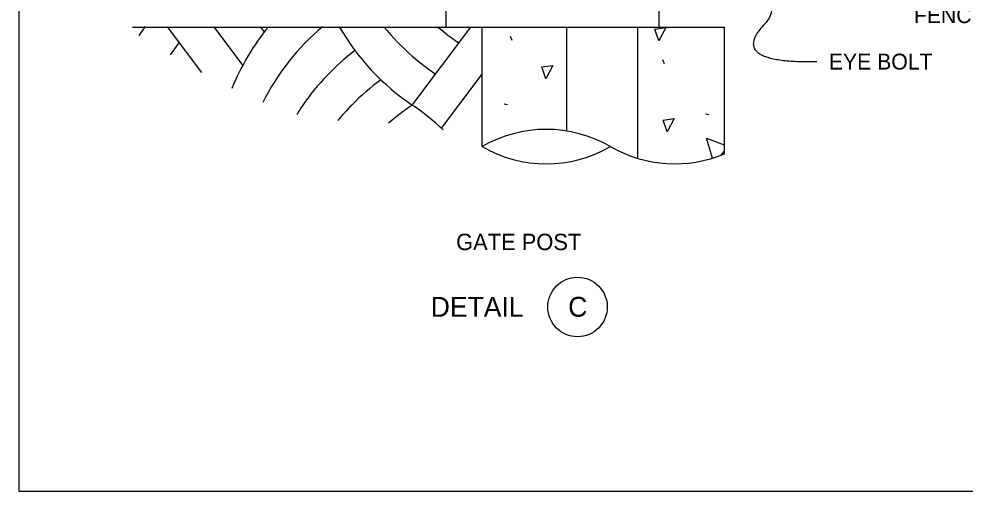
# Model space of a CAD drawing. Extents: x 99862 to 104211, y 98939 to 105076.
# Drawn here: x 99862 to 100816, y 103000 to 103475 of the extents above; entities that cross this region are included whole.
import ezdxf

# ---------------------------------------------------------------- set-up
doc = ezdxf.new("R2010")
doc.units = 0
for name, color, linetype in [('Level 1', 7, 'Continuous'), ('Level 10', 7, 'Continuous'), ('Level 15', 7, 'Continuous'), ('Level 20', 7, 'Continuous'), ('Level 6', 7, 'Continuous'), ('Level 60', 7, 'Continuous'), ('Level 7', 7, 'Continuous'), ('Level 9', 7, 'Continuous')]:
    doc.layers.add(name, color=color, linetype=linetype)

msp = doc.modelspace()

# ---------------------------------------------------------------- linework, layer by layer
at = {"layer": 'Level 1'}
msp.add_lwpolyline([(99862, 102999.5), (103151, 102999.5), (103151, 105075.5), (99862, 105075.5)], close=True, dxfattribs=at)
at = {"layer": 'Level 10'}
for p, q in [((99976.43, 103467.16), (100329.05, 103467.16)), ((99983.15, 103458.76), (99989.75, 103467.56)), ((100011.43, 103467.47), (100046.12, 103421.21)), ((100058.43, 103467.47), (100087.62, 103428.55)), ((100105.43, 103467.47), (100109.42, 103462.16)), ((100258.7, 103388.46), (100317.72, 103467.16)), ((100014.78, 103439.25), (100023.68, 103451.13)), ((100305.7, 103388.46), (100329.05, 103419.59)), ((100288.16, 103365.07), (100305.7, 103388.46))]:
    msp.add_line(p, q, dxfattribs=at)
for centre, start, end in [((100297.39, 103316.35), 140.56273, 158.07739), ((100320.9, 103285.02), 129.91883, 153.56324), ((100391.4, 103585.91), 209.85693, 236.09639), ((100414.9, 103617.24), 219.01747, 228.95992), ((100438.4, 103648.58), 229.57705, 236.09639), ((100344.4, 103253.68), 127.1006, 145.49109), ((100414.9, 103617.24), 228.95986, 236.09639), ((100367.9, 103222.34), 126.331, 135.71278), ((100344.4, 103253.68), 145.49102, 148.25498), ((100367.9, 103222.34), 135.71269, 140.72847), ((100391.4, 103191.01), 123.90361, 131.15866), ((100126, 103191.01), 46.45408, 56.09634)]:
    msp.add_arc(centre, 237.9, start, end, dxfattribs=at)
at = {"layer": 'Level 15'}
msp.add_line((100658.71, 103432.29), (100666.71, 103432.29), dxfattribs=at)
msp.add_open_spline([(100519.1, 103566.7), (100649.54, 103507.21), (100577.71, 103432.29), (100658.71, 103432.29)], degree=2, dxfattribs=at)
at = {"layer": 'Level 6'}
for p, q in [((100329.05, 103346.65), (100329.05, 103467.16)), ((100329.33, 103467.16), (100573.56, 103467.16)), ((100573.56, 103339.41), (100573.56, 103467.16)), ((100359.41, 103453.48), (100357.82, 103457.64)), ((100513.1, 103429.95), (100511.5, 103434.11)), ((100351.42, 103389.82), (100354.62, 103389.18)), ((100554.48, 103379.54), (100557.68, 103378.9))]:
    msp.add_line(p, q, dxfattribs=at)
for points in [[(100507.28, 103453.21), (100503.12, 103465.04), (100514.31, 103466.64), (100507.28, 103453.21)], [(100393.32, 103415.09), (100389.16, 103426.93), (100400.36, 103428.53), (100393.32, 103415.09)], [(100515.69, 103361.49), (100511.54, 103373.33), (100522.73, 103374.93), (100515.69, 103361.49)], [(100561.5, 103335.03), (100555.32, 103355.13), (100573.12, 103348.33)], [(100573.12, 103342.13), (100569.43, 103337.76)]]:
    msp.add_lwpolyline(points, dxfattribs=at)
for centre, start, end in [((100393.83, 103234.46), 60, 120), ((100393.83, 103458.85), 240, 300), ((100523.38, 103458.85), 240, 292.78997)]:
    msp.add_arc(centre, 129.55, start, end, dxfattribs=at)
at = {"layer": 'Level 60'}
msp.add_line((99862, 102999.5), (99862, 102999.5), dxfattribs=at)
at = {"layer": 'Level 7'}
for p, q in [((100292.63, 103498.91), (100292.63, 103467.16)), ((100507.6, 103467.16), (100507.6, 103498.91)), ((100292.63, 103467.16), (100507.6, 103467.16))]:
    msp.add_line(p, q, dxfattribs=at)
for points in [[(100414.63, 103362.33), (100414.63, 103466.73)], [(100485.94, 103466.73), (100485.94, 103334.82)]]:
    msp.add_lwpolyline(points, dxfattribs=at)
at = {"layer": 'Level 9'}
msp.add_circle((100425.36, 103185), 30, dxfattribs=at)

# ---------------------------------------------------------------- texts
at = {"layer": 'Level 20'}
for s, height, p in [('FENCE TYPE 4)', 16, (100764.45, 103471.07)), ('EYE BOLT', 16, (100678.71, 103424.29)), ('GATE POST', 16.5, (100302.85, 103242.33)), ('DETAIL', 20, (100277.29, 103175.18)), ('C', 20, (100415.91, 103175.18))]:
    msp.add_text(s, height=height, dxfattribs=at).set_placement(p)

doc.saveas('drawing.dxf')
